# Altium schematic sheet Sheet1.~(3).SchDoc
size A4
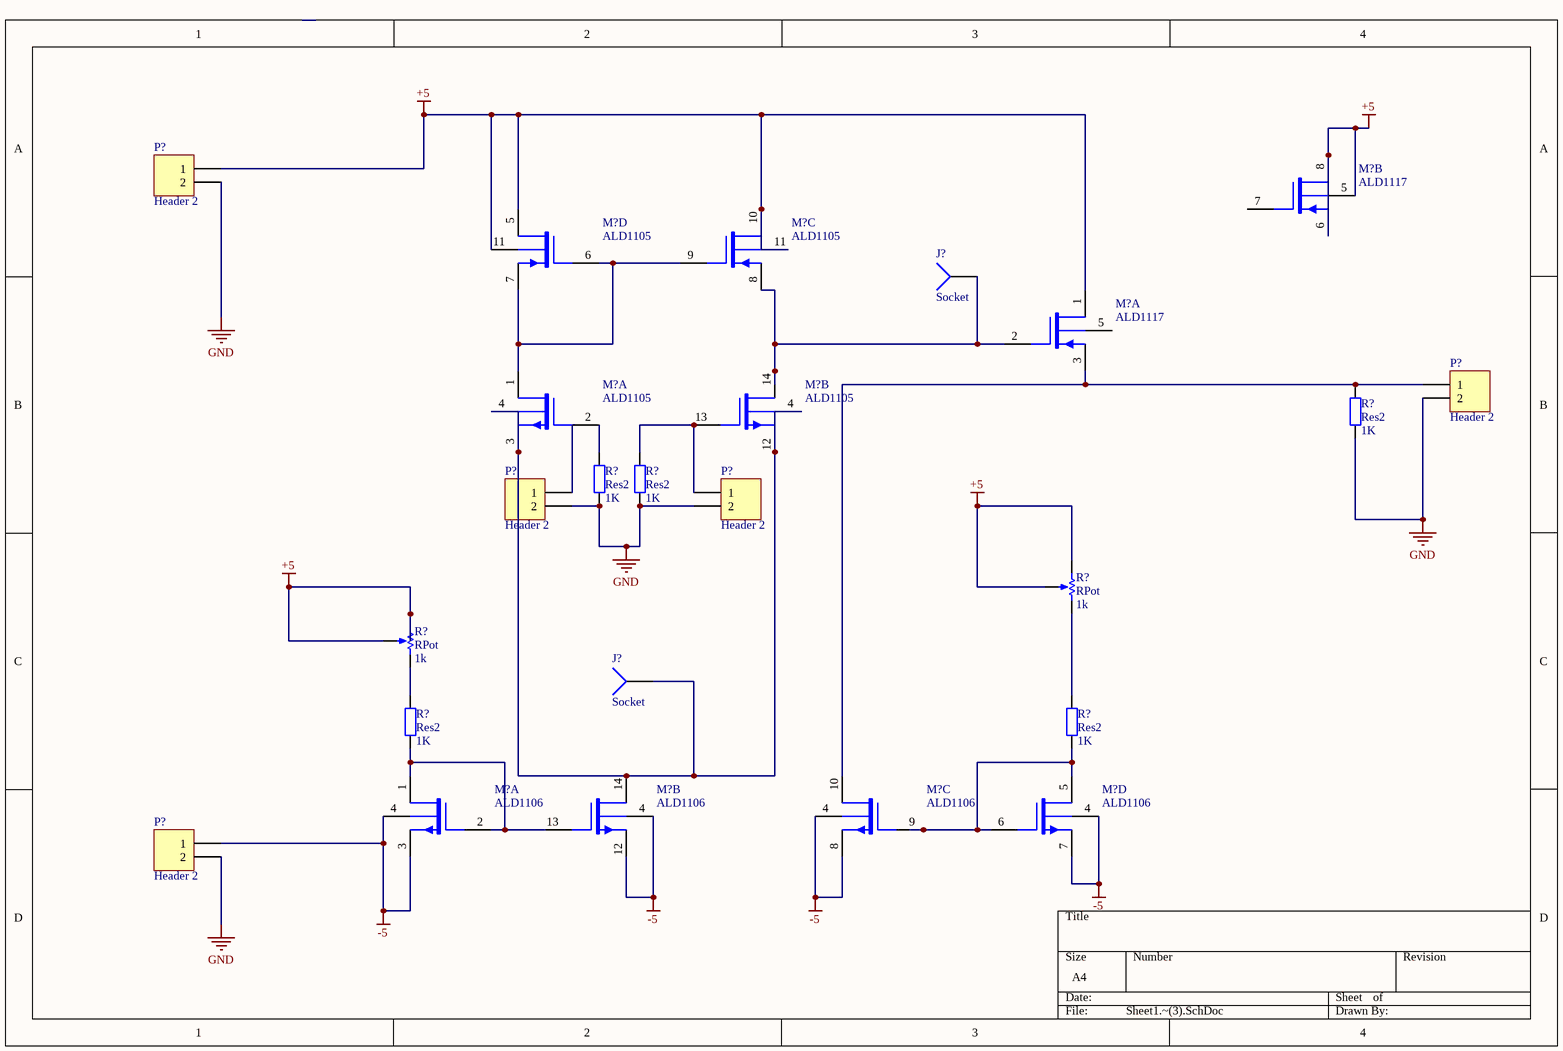
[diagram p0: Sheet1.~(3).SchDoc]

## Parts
(Parts that share a designator on the sheet are numbered #1, #2 ... from top to bottom, then left to right.)
J?#1  Socket  [PIN1]
J?#2  Socket  [PIN1]
M?#1  ALD1117  [DIP-8]  (part B of 2)
M?#2  ALD1105  [DIP-14]  (part D of 4)
M?#3  ALD1105  [DIP-14]  (part C of 4)
M?#4  ALD1117  [DIP-8]  (part A of 2)
M?#5  ALD1105  [DIP-14]  (part A of 4)
M?#6  ALD1105  [DIP-14]  (part B of 4)
M?#7  ALD1106  [DIP-14]  (part A of 4)
M?#8  ALD1106  [DIP-14]  (part B of 4)
M?#9  ALD1106  [DIP-14]  (part C of 4)
M?#10  ALD1106  [DIP-14]  (part D of 4)
P?#1  Header 2  [HDR1X2]
P?#2  Header 2  [HDR1X2]
P?#3  Header 2  [HDR1X2]
P?#4  Header 2  [HDR1X2]
P?#5  Header 2  [HDR1X2]
R?#1  Res2  value 1K  [AXIAL-0.4]
R?#2  Res2  value 1K  [AXIAL-0.4]
R?#3  Res2  value 1K  [AXIAL-0.4]
R?#4  RPot  value 1k  [VR5]
R?#5  RPot  value 1k  [VR5]
R?#6  Res2  value 1K  [AXIAL-0.4]
R?#7  Res2  value 1K  [AXIAL-0.4]

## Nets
+5: M?#1.5(V+) M?#1.6(SP2) M?#1.8(DP2) M?#2.5(DP1) M?#2.11(V+) M?#3.10(DP2) M?#3.11(V+) M?#4.1(DP1) P?#1.1 R?#4.1(TOP) R?#4.2(TAP) R?#5.1(TOP) R?#5.2(TAP)
-5: M?#7.3(SN1) M?#7.4(V-) M?#8.4(V-) M?#8.12(SN2) M?#9.4(V-) M?#9.8(SN3) M?#10.4(V-) M?#10.7(SN4) P?#5.1
GND: P?#1.2 P?#2.2 P?#3.2 P?#4.2 P?#5.2 R?#1.1 R?#2.1 R?#3.1
NetJ?#1_1: J?#1.1 M?#3.8(SP2) M?#4.2(GP1) M?#6.14(DN2)
NetJ?#2_1: J?#2.1 M?#5.3(SN1) M?#5.4(V-) M?#6.4(V-) M?#6.12(SN2) M?#8.14(DN2)
NetM?#2_6: M?#2.6(GP1) M?#2.7(SP1) M?#3.9(GP2) M?#5.1(DN1)
NetM?#4_3: M?#4.3(SP1) M?#9.10(DN3) P?#2.1 R?#1.2
NetM?#5_2: M?#5.2(GN1) R?#2.2
NetM?#6_13: M?#6.13(GN2) P?#4.1 R?#3.2
NetM?#7_1: M?#7.1(DN1) M?#7.2(GN1) M?#8.13(GN2) R?#6.1
NetM?#9_9: M?#9.9(GN3) M?#10.5(DN4) M?#10.6(GN4) R?#7.1
NetR?#4_3: R?#4.3(BOT) R?#7.2
NetR?#5_3: R?#5.3(BOT) R?#6.2

Not connected (* = marked no-connect by the designer): M?#1 7(GP2); M?#4 5(V+); P?#3 1

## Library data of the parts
M?#1 M?#4 = ALD1117: Dual P-channel matched MOSFET array
M?#2 M?#3 M?#5 M?#6 = ALD1105: Dual P-channel and dual N-channel matched MOSFET array
M?#7-M?#10 = ALD1106: Quad N-channel matched MOSFET array
P?#1-P?#5 = Header 2: Header, 2-Pin
R?#1-R?#3 R?#6 R?#7 = Res2: Resistor
R?#4 R?#5 = RPot: Potentiometer; Sim Note: Enter the Resistance value and the set point into parameter fields.; Set Position: 0.5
